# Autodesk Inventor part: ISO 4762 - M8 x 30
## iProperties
Comments: To add or edit properties for Autodesk Inventor files, use iProperties.
Created: 2004-08
Part Number: ISO 4762 - M8 x 30
Vendor: Autodesk Inc.
Document SubType Name: Modeling
Designer: John Blackburn
Material: Default
Description: Hexagon Socket Head Cap Screw
Standard: ISO 4762
Size Designation: M8 x 30
Alert: To add or edit properties for Autodesk Inventor files, use iProperties.
Control State: 0
Master: False
Checked Out: False
Shininess: 64.0
Length Units: 11269
Angle Units: 11279
Time Units: 11290
Mass Units: 11283
Length Display Precision: 3
Angle Display Precision: 2
Compacted: True
EGR: 1
Density: 0.0
Volumn: 0.0
Area: 0.0
PropertySet Name: Model Information
Author: John Blackburn
Revision Number: 8
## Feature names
1. Body [Revolution]
2. Slot [Extrusion]
3. Fillet1
4. Chamfer1
